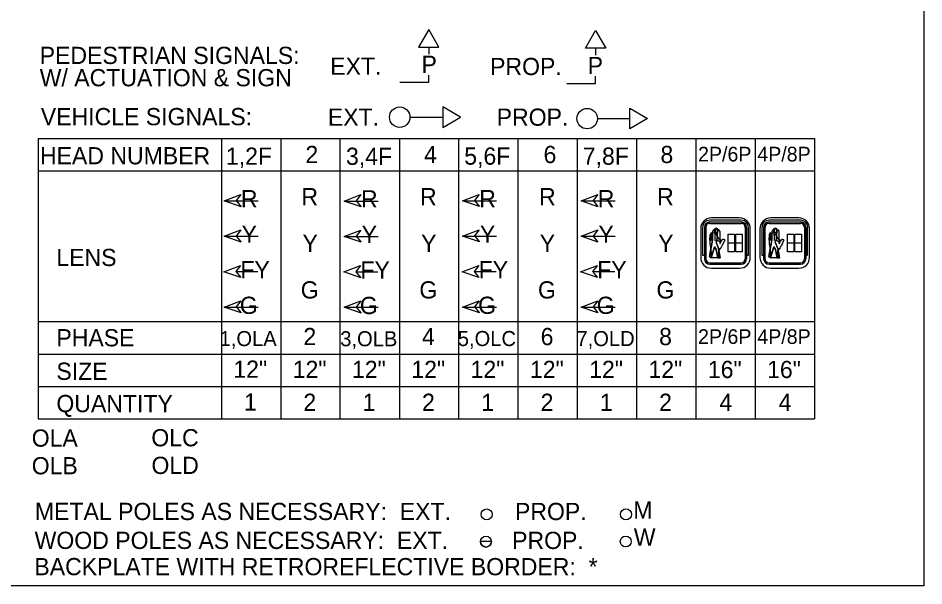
# Model space of a CAD drawing. Extents: x 0 to 3.01, y -0.05 to 1.83.
# Drawn here: x 0.2563 to 0.7077, y 1.2823 to 1.5653 of the extents above; entities that cross this region are included whole.
import ezdxf

# ---------------------------------------------------------------- set-up
doc = ezdxf.new("R2010")
doc.units = 0
for name, color, linetype in [('Default', 7, 'Continuous'), ('TR_TS_Border', 7, 'Continuous'), ('TR_TS_Phase1', 7, 'Continuous'), ('TR_TS_Phase2', 7, 'Continuous'), ('TR_TS_Phase3', 7, 'Continuous'), ('TR_TS_Phase4', 7, 'Continuous'), ('TR_TS_Phase5', 7, 'Continuous'), ('TR_TS_Phase6', 7, 'Continuous'), ('TR_TS_Phase7', 7, 'Continuous'), ('TR_TS_Phase8', 7, 'Continuous'), ('TR_TS_Text', 7, 'Continuous')]:
    doc.layers.add(name, color=color, linetype=linetype)

msp = doc.modelspace()

# ---------------------------------------------------------------- linework, layer by layer
at = {"layer": 'TR_TS_Border'}
for p, q in [((0.46095, 1.55972), (0.45582, 1.55087)), ((0.46607, 1.55087), (0.46095, 1.55972)), ((0.53902, 1.55029), (0.54415, 1.55914)), ((0.54415, 1.55914), (0.54927, 1.55029)), ((0.45582, 1.55087), (0.46607, 1.55087)), ((0.46094, 1.55087), (0.46094, 1.54739)), ((0.54927, 1.55029), (0.53902, 1.55029)), ((0.54414, 1.55029), (0.54414, 1.54681)), ((0.46094, 1.53335), (0.46094, 1.53689)), ((0.54414, 1.53278), (0.54414, 1.53632)), ((0.44653, 1.53335), (0.46094, 1.53335)), ((0.52973, 1.53278), (0.54414, 1.53278)), ((0.47683, 1.51599), (0.46798, 1.52105)), ((0.46798, 1.52105), (0.46798, 1.51087)), ((0.56115, 1.51017), (0.56116, 1.52035)), ((0.56116, 1.52035), (0.57001, 1.51529)), ((0.45159, 1.516), (0.46771, 1.516)), ((0.46798, 1.51087), (0.47683, 1.51599)), ((0.54503, 1.51529), (0.56116, 1.51529)), ((0.57001, 1.51529), (0.56115, 1.51017)), ((0.26627, 1.50537), (0.65319, 1.50537)), ((0.26627, 1.50537), (0.26627, 1.36564)), ((0.35762, 1.50537), (0.35762, 1.36564)), ((0.35762, 1.50537), (0.35762, 1.36564)), ((0.38721, 1.50537), (0.38721, 1.36564)), ((0.41674, 1.50537), (0.41674, 1.36564)), ((0.44632, 1.50537), (0.44632, 1.36564)), ((0.47585, 1.50537), (0.47585, 1.36564)), ((0.50544, 1.50537), (0.50544, 1.36564)), ((0.53496, 1.50537), (0.53496, 1.36564)), ((0.56455, 1.50537), (0.56455, 1.36564)), ((0.59407, 1.50537), (0.59407, 1.36564)), ((0.62366, 1.50537), (0.62366, 1.36564)), ((0.62366, 1.50537), (0.62366, 1.36564)), ((0.65319, 1.50537), (0.65319, 1.36564)), ((0.65319, 1.50537), (0.65319, 1.36564)), ((0.26627, 1.48924), (0.65319, 1.48924)), ((0.26627, 1.41401), (0.65319, 1.41401)), ((0.26627, 1.39789), (0.65319, 1.39789)), ((0.26627, 1.38177), (0.65319, 1.38177)), ((0.26627, 1.36564), (0.65319, 1.36564)), ((0.49219, 1.30439), (0.48676, 1.30439))]:
    msp.add_line(p, q, dxfattribs=at)
msp.add_lwpolyline([(0.20262, 1.70195), (0.70772, 1.70191), (0.70768, 1.2823), (0.20258, 1.28235)], close=True, dxfattribs=at)
for centre, radius in [((0.44651, 1.51592), 0.0051), ((0.53995, 1.51522), 0.0051), ((0.48986, 1.31794), 0.00273), ((0.55926, 1.31796), 0.00272), ((0.48947, 1.3044), 0.00273), ((0.55914, 1.30442), 0.00272)]:
    msp.add_circle(centre, radius, dxfattribs=at)
msp.add_arc((0.48947, 1.30439), 0.00272, 179.995, 359.995, dxfattribs=at)
at = {"layer": 'TR_TS_Phase1'}
for p, q in [((0.35905, 1.47423), (0.36738, 1.4774)), ((0.36738, 1.4774), (0.36499, 1.47433)), ((0.35905, 1.47423), (0.37596, 1.47423)), ((0.36746, 1.47133), (0.35905, 1.47423)), ((0.36499, 1.47433), (0.36746, 1.47133)), ((0.35905, 1.45659), (0.36738, 1.45976)), ((0.36738, 1.45976), (0.36499, 1.4567)), ((0.35905, 1.45659), (0.37596, 1.45659)), ((0.36746, 1.4537), (0.35905, 1.45659)), ((0.36499, 1.4567), (0.36746, 1.4537)), ((0.35883, 1.43887), (0.36717, 1.44204)), ((0.36717, 1.44204), (0.36478, 1.43898)), ((0.36725, 1.43598), (0.35883, 1.43887)), ((0.36478, 1.43898), (0.37582, 1.43898)), ((0.36478, 1.43898), (0.36725, 1.43598)), ((0.35905, 1.42124), (0.36738, 1.42441)), ((0.36738, 1.42441), (0.36499, 1.42134)), ((0.35905, 1.42124), (0.37596, 1.42124)), ((0.36746, 1.41835), (0.35905, 1.42124)), ((0.36499, 1.42134), (0.36746, 1.41835))]:
    msp.add_line(p, q, dxfattribs=at)
at = {"layer": 'TR_TS_Phase3'}
for p, q in [((0.41888, 1.47415), (0.42721, 1.47732)), ((0.42721, 1.47732), (0.42482, 1.47425)), ((0.41888, 1.47415), (0.43579, 1.47415)), ((0.42729, 1.47125), (0.41888, 1.47415)), ((0.42482, 1.47425), (0.42729, 1.47125)), ((0.41888, 1.45651), (0.42721, 1.45968)), ((0.42721, 1.45968), (0.42482, 1.45662)), ((0.41888, 1.45651), (0.43579, 1.45651)), ((0.42729, 1.45362), (0.41888, 1.45651)), ((0.42482, 1.45662), (0.42729, 1.45362)), ((0.41866, 1.43879), (0.427, 1.44196)), ((0.427, 1.44196), (0.42461, 1.4389)), ((0.42708, 1.4359), (0.41866, 1.43879)), ((0.42461, 1.4389), (0.43565, 1.4389)), ((0.42461, 1.4389), (0.42708, 1.4359)), ((0.41888, 1.42116), (0.42721, 1.42433)), ((0.42721, 1.42433), (0.42482, 1.42126)), ((0.41888, 1.42116), (0.43579, 1.42116)), ((0.42729, 1.41827), (0.41888, 1.42116)), ((0.42482, 1.42126), (0.42729, 1.41827))]:
    msp.add_line(p, q, dxfattribs=at)
at = {"layer": 'TR_TS_Phase5'}
for p, q in [((0.47781, 1.47425), (0.48615, 1.47742)), ((0.48615, 1.47742), (0.48376, 1.47435)), ((0.47781, 1.47425), (0.49472, 1.47425)), ((0.48623, 1.47135), (0.47781, 1.47425)), ((0.48376, 1.47435), (0.48623, 1.47135)), ((0.47781, 1.45661), (0.48615, 1.45978)), ((0.48615, 1.45978), (0.48376, 1.45672)), ((0.47781, 1.45661), (0.49472, 1.45661)), ((0.48623, 1.45372), (0.47781, 1.45661)), ((0.48376, 1.45672), (0.48623, 1.45372)), ((0.4776, 1.43889), (0.48593, 1.44206)), ((0.48593, 1.44206), (0.48354, 1.439)), ((0.48601, 1.436), (0.4776, 1.43889)), ((0.48354, 1.439), (0.49459, 1.439)), ((0.48354, 1.439), (0.48601, 1.436)), ((0.47781, 1.42126), (0.48615, 1.42443)), ((0.48615, 1.42443), (0.48376, 1.42136)), ((0.47781, 1.42126), (0.49472, 1.42126)), ((0.48623, 1.41837), (0.47781, 1.42126)), ((0.48376, 1.42136), (0.48623, 1.41837))]:
    msp.add_line(p, q, dxfattribs=at)
at = {"layer": 'TR_TS_Phase7'}
for p, q in [((0.53688, 1.47423), (0.54522, 1.4774)), ((0.54522, 1.4774), (0.54283, 1.47433)), ((0.53688, 1.47423), (0.55379, 1.47423)), ((0.5453, 1.47133), (0.53688, 1.47423)), ((0.54283, 1.47433), (0.5453, 1.47133)), ((0.53688, 1.45659), (0.54522, 1.45976)), ((0.54522, 1.45976), (0.54283, 1.4567)), ((0.53688, 1.45659), (0.55379, 1.45659)), ((0.5453, 1.4537), (0.53688, 1.45659)), ((0.54283, 1.4567), (0.5453, 1.4537)), ((0.53666, 1.43887), (0.545, 1.44204)), ((0.545, 1.44204), (0.54261, 1.43898)), ((0.54508, 1.43598), (0.53666, 1.43887)), ((0.54261, 1.43898), (0.55366, 1.43898)), ((0.54261, 1.43898), (0.54508, 1.43598)), ((0.53688, 1.42124), (0.54522, 1.42441)), ((0.54522, 1.42441), (0.54283, 1.42134)), ((0.53688, 1.42124), (0.55379, 1.42124)), ((0.5453, 1.41835), (0.53688, 1.42124)), ((0.54283, 1.42134), (0.5453, 1.41835))]:
    msp.add_line(p, q, dxfattribs=at)
at = {"layer": 'TR_TS_Text'}
for p, q in [((0.61669, 1.46461), (0.60101, 1.46461)), ((0.60101, 1.46369), (0.61669, 1.46369)), ((0.60101, 1.46302), (0.61669, 1.46302)), ((0.61586, 1.46569), (0.60184, 1.46569)), ((0.64622, 1.46461), (0.63054, 1.46461)), ((0.63054, 1.46369), (0.64622, 1.46369)), ((0.63054, 1.46302), (0.64622, 1.46302)), ((0.64538, 1.46569), (0.63137, 1.46569)), ((0.59651, 1.46035), (0.59651, 1.44601)), ((0.59742, 1.46102), (0.59742, 1.44717)), ((0.59834, 1.46102), (0.59834, 1.44534)), ((0.59901, 1.46102), (0.59901, 1.44534)), ((0.60123, 1.45729), (0.6027, 1.45819)), ((0.6026, 1.45448), (0.60256, 1.45913)), ((0.6027, 1.45819), (0.6027, 1.4582)), ((0.60349, 1.45913), (0.60352, 1.45449)), ((0.60369, 1.45449), (0.60382, 1.45986)), ((0.60475, 1.45986), (0.60461, 1.45445)), ((0.60478, 1.45445), (0.60505, 1.45922)), ((0.60596, 1.4591), (0.60596, 1.4531)), ((0.61869, 1.46102), (0.61869, 1.44534)), ((0.61936, 1.46102), (0.61936, 1.44534)), ((0.62028, 1.44717), (0.62028, 1.46102)), ((0.6212, 1.44601), (0.6212, 1.46035)), ((0.62603, 1.46035), (0.62603, 1.44601)), ((0.62695, 1.46102), (0.62695, 1.44717)), ((0.62787, 1.46102), (0.62787, 1.44534)), ((0.62853, 1.46102), (0.62853, 1.44534)), ((0.63075, 1.45729), (0.63222, 1.45819)), ((0.63212, 1.45448), (0.63209, 1.45913)), ((0.63222, 1.45819), (0.63222, 1.4582)), ((0.63301, 1.45913), (0.63305, 1.45449)), ((0.63322, 1.45449), (0.63335, 1.45986)), ((0.63427, 1.45986), (0.63414, 1.45445)), ((0.63431, 1.45445), (0.63458, 1.45922)), ((0.63548, 1.4591), (0.63548, 1.4531)), ((0.64822, 1.46102), (0.64822, 1.44534)), ((0.64889, 1.46102), (0.64889, 1.44534)), ((0.6498, 1.44717), (0.6498, 1.46102)), ((0.65072, 1.44601), (0.65072, 1.46035)), ((0.60093, 1.44657), (0.60227, 1.45378)), ((0.60101, 1.45458), (0.60123, 1.45729)), ((0.60164, 1.45461), (0.60101, 1.45458)), ((0.60128, 1.45245), (0.60133, 1.45762)), ((0.60194, 1.45704), (0.60164, 1.45461)), ((0.60233, 1.45704), (0.60194, 1.45704)), ((0.60208, 1.45568), (0.60233, 1.45704)), ((0.60229, 1.45762), (0.60243, 1.45448)), ((0.60243, 1.45448), (0.6026, 1.45448)), ((0.60352, 1.45449), (0.60369, 1.45449)), ((0.60415, 1.45359), (0.6054, 1.45044)), ((0.6051, 1.45433), (0.6044, 1.45502)), ((0.60445, 1.4574), (0.60535, 1.45525)), ((0.60461, 1.45445), (0.60478, 1.45445)), ((0.60631, 1.45384), (0.6051, 1.45433)), ((0.60535, 1.45525), (0.6066, 1.45455)), ((0.60627, 1.453), (0.60673, 1.45402)), ((0.6066, 1.45455), (0.60631, 1.45384)), ((0.60848, 1.45488), (0.607, 1.4516)), ((0.63045, 1.44657), (0.63179, 1.45378)), ((0.63054, 1.45458), (0.63075, 1.45729)), ((0.63116, 1.45461), (0.63054, 1.45458)), ((0.6308, 1.45245), (0.63085, 1.45762)), ((0.63147, 1.45704), (0.63116, 1.45461)), ((0.63185, 1.45704), (0.63147, 1.45704)), ((0.6316, 1.45568), (0.63185, 1.45704)), ((0.63182, 1.45762), (0.63196, 1.45448)), ((0.63196, 1.45448), (0.63212, 1.45448)), ((0.63305, 1.45449), (0.63322, 1.45449)), ((0.63368, 1.45359), (0.63492, 1.45044)), ((0.63463, 1.45433), (0.63392, 1.45502)), ((0.63398, 1.4574), (0.63487, 1.45525)), ((0.63414, 1.45445), (0.63431, 1.45445)), ((0.63584, 1.45384), (0.63463, 1.45433)), ((0.63487, 1.45525), (0.63612, 1.45455)), ((0.6358, 1.453), (0.63626, 1.45402)), ((0.63612, 1.45455), (0.63584, 1.45384)), ((0.638, 1.45488), (0.63652, 1.4516)), ((0.60179, 1.44921), (0.60162, 1.44964)), ((0.60333, 1.45137), (0.60172, 1.44584)), ((0.60424, 1.45001), (0.60333, 1.45137)), ((0.60504, 1.44584), (0.60424, 1.45001)), ((0.60529, 1.44897), (0.60529, 1.44647)), ((0.6054, 1.45044), (0.60628, 1.44584)), ((0.60657, 1.45088), (0.60543, 1.44943)), ((0.61015, 1.45323), (0.61339, 1.45323)), ((0.61395, 1.45323), (0.61719, 1.45323)), ((0.63131, 1.44921), (0.63114, 1.44964)), ((0.63286, 1.45137), (0.63125, 1.44584)), ((0.63377, 1.45001), (0.63286, 1.45137)), ((0.63457, 1.44584), (0.63377, 1.45001)), ((0.63481, 1.44897), (0.63481, 1.44647)), ((0.63492, 1.45044), (0.63581, 1.44584)), ((0.6361, 1.45088), (0.63496, 1.44943)), ((0.63967, 1.45323), (0.64292, 1.45323)), ((0.64347, 1.45323), (0.64672, 1.45323)), ((0.59742, 1.44717), (0.59834, 1.44717)), ((0.60172, 1.44584), (0.60093, 1.44657)), ((0.60568, 1.44584), (0.60153, 1.44584)), ((0.60193, 1.44647), (0.60193, 1.44843)), ((0.60628, 1.44584), (0.60504, 1.44584)), ((0.6194, 1.44717), (0.62028, 1.44717)), ((0.62695, 1.44717), (0.62786, 1.44717)), ((0.63125, 1.44584), (0.63045, 1.44657)), ((0.63521, 1.44584), (0.63106, 1.44584)), ((0.63145, 1.44647), (0.63145, 1.44843)), ((0.63581, 1.44584), (0.63457, 1.44584)), ((0.64893, 1.44717), (0.6498, 1.44717)), ((0.60101, 1.44334), (0.61669, 1.44334)), ((0.60101, 1.44267), (0.61669, 1.44267)), ((0.60184, 1.44067), (0.61586, 1.44067)), ((0.63054, 1.44334), (0.64622, 1.44334)), ((0.63054, 1.44267), (0.64622, 1.44267)), ((0.63137, 1.44067), (0.64538, 1.44067))]:
    msp.add_line(p, q, dxfattribs=at)
for points in [[(0.6027, 1.4582), (0.60123, 1.45729), (0.60101, 1.45458), (0.60164, 1.45461), (0.60194, 1.45704), (0.60233, 1.45704), (0.60208, 1.45568)], [(0.63222, 1.4582), (0.63075, 1.45729), (0.63054, 1.45458), (0.63116, 1.45461), (0.63147, 1.45704), (0.63185, 1.45704), (0.6316, 1.45568)], [(0.60227, 1.45378), (0.60093, 1.44657), (0.60172, 1.44584), (0.60333, 1.45137), (0.60424, 1.45001), (0.60504, 1.44584), (0.60628, 1.44584), (0.6054, 1.45044), (0.60415, 1.45359)], [(0.6044, 1.45502), (0.6051, 1.45433), (0.60631, 1.45384), (0.6066, 1.45455), (0.60535, 1.45525), (0.60445, 1.4574)], [(0.63179, 1.45378), (0.63045, 1.44657), (0.63125, 1.44584), (0.63286, 1.45137), (0.63377, 1.45001), (0.63457, 1.44584), (0.63581, 1.44584), (0.63492, 1.45044), (0.63368, 1.45359)], [(0.63392, 1.45502), (0.63463, 1.45433), (0.63584, 1.45384), (0.63612, 1.45455), (0.63487, 1.45525), (0.63398, 1.4574)]]:
    msp.add_lwpolyline(points, dxfattribs=at)
for points in [[(0.61015, 1.45757), (0.61339, 1.45757), (0.61339, 1.4489), (0.61015, 1.4489)], [(0.61395, 1.45757), (0.61719, 1.45757), (0.61719, 1.4489), (0.61395, 1.4489)], [(0.63967, 1.45757), (0.64292, 1.45757), (0.64292, 1.4489), (0.63967, 1.4489)], [(0.64347, 1.45757), (0.64672, 1.45757), (0.64672, 1.4489), (0.64347, 1.4489)]]:
    msp.add_lwpolyline(points, close=True, dxfattribs=at)
for centre in [(0.6042, 1.4595), (0.63372, 1.4595)]:
    msp.add_circle(centre, 0.00104, dxfattribs=at)
for centre, radius, start, end in [((0.60184, 1.46035), 0.00534, 90, 180), ((0.60101, 1.46102), 0.00359, 90, 180), ((0.60101, 1.46102), 0.00267, 90, 180), ((0.60101, 1.46102), 0.002, 90, 180), ((0.61586, 1.46035), 0.00534, 360, 90), ((0.61669, 1.46102), 0.00359, 360, 90), ((0.61669, 1.46102), 0.00267, 360, 90), ((0.61669, 1.46102), 0.002, 360, 90), ((0.63137, 1.46035), 0.00534, 90, 180), ((0.63054, 1.46102), 0.00359, 90, 180), ((0.63054, 1.46102), 0.00267, 90, 180), ((0.63054, 1.46102), 0.002, 90, 180), ((0.64538, 1.46035), 0.00534, 360, 90), ((0.64622, 1.46102), 0.00359, 360, 90), ((0.64622, 1.46102), 0.00267, 360, 90), ((0.64622, 1.46102), 0.002, 360, 90), ((0.60315, 1.45686), 0.00141, 22.5543, 108.8346), ((0.60315, 1.45686), 0.00141, 22.5543, 108.8346), ((0.6042, 1.4595), 0.00104, 360, 180), ((0.6042, 1.4595), 0.00104, 180, 360), ((0.63268, 1.45686), 0.00141, 22.5543, 108.8346), ((0.63268, 1.45686), 0.00141, 22.5543, 108.8346), ((0.63372, 1.4595), 0.00104, 360, 180), ((0.63372, 1.4595), 0.00104, 180, 360), ((0.60937, 1.45546), 0.00729, 178.2568, 193.3072), ((0.60937, 1.45546), 0.00729, 178.2568, 193.3072), ((0.62269, 1.45117), 0.0187, 168.1276, 172.5821), ((0.62269, 1.45117), 0.0187, 168.1276, 172.5821), ((0.63889, 1.45546), 0.00729, 178.2568, 193.3072), ((0.63889, 1.45546), 0.00729, 178.2568, 193.3072), ((0.65222, 1.45117), 0.0187, 168.1276, 172.5821), ((0.65222, 1.45117), 0.0187, 168.1276, 172.5821), ((0.60184, 1.44601), 0.00534, 180, 270), ((0.60101, 1.44534), 0.00267, 180, 270), ((0.60101, 1.44534), 0.002, 180, 270), ((0.61586, 1.44601), 0.00534, 270, 360), ((0.61669, 1.44534), 0.00267, 270, 360), ((0.61669, 1.44534), 0.002, 270, 360), ((0.63137, 1.44601), 0.00534, 180, 270), ((0.63054, 1.44534), 0.00267, 180, 270), ((0.63054, 1.44534), 0.002, 180, 270), ((0.64538, 1.44601), 0.00534, 270, 360), ((0.64622, 1.44534), 0.00267, 270, 360), ((0.64622, 1.44534), 0.002, 270, 360)]:
    msp.add_arc(centre, radius, start, end, dxfattribs=at)
for centre, major_axis, start_param, end_param in [((0.60181, 1.45762), (0, 0.000619), 4.712477, 7.854069), ((0.60303, 1.45913), (0, 0.000592), 4.712394, 7.853977), ((0.60428, 1.45986), (0, 0.000592), 4.71238, 7.853968), ((0.6055, 1.45914), (0, 0.000581), 4.648575, 7.711685), ((0.63134, 1.45762), (0, 0.000619), 4.712477, 7.854069), ((0.63255, 1.45913), (0, 0.000592), 4.712394, 7.853977), ((0.63381, 1.45986), (0, 0.000592), 4.71238, 7.853968), ((0.63503, 1.45914), (0, 0.000581), 4.648575, 7.711685), ((0.60792, 1.45338), (0, 0.00165), 5.840541, 7.460675), ((0.63745, 1.45338), (0, 0.00165), 5.840541, 7.460675), ((0.60799, 1.45234), (0, 0.00861), 1.557894, 1.890309), ((0.60059, 1.44843), (0, 0.00172), 4.712389, 5.179357), ((0.60579, 1.44897), (0, -0.000646), 3.926991, 4.712389), ((0.60613, 1.4531), (0, -0.000215), 4.712389, 7.330375), ((0.60467, 1.45332), (0, -0.00344), 0.785398, 1.047195), ((0.63752, 1.45234), (0, 0.00861), 1.557894, 1.890309), ((0.63011, 1.44843), (0, 0.00172), 4.712389, 5.179357), ((0.63531, 1.44897), (0, -0.000646), 3.926991, 4.712389), ((0.63565, 1.4531), (0, -0.000215), 4.712389, 7.330375), ((0.6342, 1.45332), (0, -0.00344), 0.785398, 1.047195), ((0.60143, 1.44647), (0, 0.000646), 3.359088, 4.712389), ((0.60579, 1.44647), (0, -0.000646), 4.712389, 6.06569), ((0.63095, 1.44647), (0, 0.000646), 3.359088, 4.712389), ((0.63531, 1.44647), (0, -0.000646), 4.712389, 6.06569)]:
    msp.add_ellipse(centre, major_axis=major_axis, ratio=0.780287, start_param=start_param, end_param=end_param, dxfattribs=at)

# ---------------------------------------------------------------- texts
at = {"layer": 'Default'}
for s, p in [('PEDESTRIAN SIGNALS:', (0.2671, 1.54245)), ('W/ ACTUATION & SIGN', (0.2671, 1.53134))]:
    msp.add_text(s, height=0.0085848, dxfattribs=at).set_placement(p)
at = {"layer": 'TR_TS_Border'}
for s, height, p in [('EXT.', 0.008585, (0.41188, 1.53706)), ('P', 0.00858, (0.45737, 1.538)), ('PROP.', 0.008585, (0.49154, 1.53692)), ('P', 0.00858, (0.54017, 1.53742)), ('VEHICLE SIGNALS:', 0.0085848, (0.26766, 1.51193)), ('EXT.', 0.008585, (0.41069, 1.51167)), ('PROP.', 0.008585, (0.49483, 1.51166)), ('METAL POLES AS NECESSARY:  EXT.          PROP.', 0.0085848, (0.26471, 1.31513)), ('M', 0.00858, (0.5629, 1.31581)), ('WOOD POLES AS NECESSARY:  EXT.          PROP.', 0.0085848, (0.26457, 1.30072)), ('W', 0.00858, (0.56316, 1.30235)), ('BACKPLATE WITH RETROREFLECTIVE BORDER:  *', 0.0085848, (0.26445, 1.28762))]:
    msp.add_text(s, height=height, rotation=359.995, dxfattribs=at).set_placement(p)
for s, height, p in [('HEAD NUMBER', 0.0085848, (0.26723, 1.49243)), ('LENS', 0.008585, (0.27541, 1.44172)), ('PHASE', 0.008585, (0.27541, 1.4017)), ('SIZE', 0.008585, (0.27541, 1.38501)), ('QUANTITY', 0.008585, (0.27541, 1.36889)), ('OLA', 0.008578, (0.26313, 1.35171)), ('OLC', 0.008578, (0.32273, 1.35188)), ('OLB', 0.008578, (0.26313, 1.33792)), ('OLD', 0.008578, (0.32281, 1.33809))]:
    msp.add_text(s, height=height, dxfattribs=at).set_placement(p)
at = {"layer": 'TR_TS_Phase1'}
for s, height, p in [('1,2F', 0.008585, (0.3599, 1.49223)), ('R', 0.00858, (0.36737, 1.47104)), (' Y ', 0.008585, (0.36451, 1.45331)), ('FY', 0.008585, (0.36709, 1.43559)), (' G ', 0.008585, (0.36363, 1.41787)), ('1,OLA', 0.007506, (0.35675, 1.40183))]:
    msp.add_text(s, height=height, rotation=360, dxfattribs=at).set_placement(p)
for s, p in [('12"', (0.3636, 1.38603)), (' 1 ', (0.36573, 1.36965))]:
    msp.add_text(s, height=0.008585, dxfattribs=at).set_placement(p)
at = {"layer": 'TR_TS_Phase2'}
for s, height, p in [('2', 0.00858, (0.39951, 1.49306)), (' R ', 0.008585, (0.39432, 1.47205)), (' Y ', 0.008585, (0.39487, 1.4488)), (' G ', 0.008585, (0.39399, 1.42555)), (' 2 ', 0.008585, (0.39532, 1.4023)), ('12"', 0.008585, (0.39318, 1.38592)), (' 2 ', 0.008585, (0.39532, 1.36954))]:
    msp.add_text(s, height=height, dxfattribs=at).set_placement(p)
at = {"layer": 'TR_TS_Phase3'}
for s, height, p in [('3,4F', 0.008585, (0.41973, 1.49215)), ('R', 0.00858, (0.4272, 1.47096)), (' Y ', 0.008585, (0.42434, 1.45323)), ('FY', 0.008585, (0.42692, 1.43551)), (' G ', 0.008585, (0.42346, 1.41779)), ('3,OLB', 0.007506, (0.41687, 1.40175))]:
    msp.add_text(s, height=height, rotation=360, dxfattribs=at).set_placement(p)
for s, p in [('12"', (0.42271, 1.38592)), (' 1 ', (0.42484, 1.36954))]:
    msp.add_text(s, height=0.008585, dxfattribs=at).set_placement(p)
at = {"layer": 'TR_TS_Phase4'}
for s, height, p in [('4', 0.00858, (0.45864, 1.49306)), (' R ', 0.008585, (0.45343, 1.47205)), (' Y ', 0.008585, (0.45398, 1.4488)), (' G ', 0.008585, (0.4531, 1.42555)), (' 4 ', 0.008585, (0.45443, 1.4023)), ('12"', 0.008585, (0.4523, 1.38592)), (' 2 ', 0.008585, (0.45443, 1.36954))]:
    msp.add_text(s, height=height, dxfattribs=at).set_placement(p)
at = {"layer": 'TR_TS_Phase5'}
for s, height, p in [('5,6F', 0.008585, (0.47866, 1.49225)), ('R', 0.00858, (0.48614, 1.47106)), (' Y ', 0.008585, (0.48327, 1.45333)), ('FY', 0.008585, (0.48585, 1.43561)), (' G ', 0.008585, (0.48239, 1.41789)), ('5,OLC', 0.007506, (0.47544, 1.40185))]:
    msp.add_text(s, height=height, rotation=360, dxfattribs=at).set_placement(p)
for s, p in [('12"', (0.48182, 1.38592)), (' 1 ', (0.48395, 1.36954))]:
    msp.add_text(s, height=0.008585, dxfattribs=at).set_placement(p)
at = {"layer": 'TR_TS_Phase6'}
for s, height, p in [('6', 0.00858, (0.51818, 1.49306)), ('R', 0.00858, (0.51596, 1.47205)), (' Y ', 0.008585, (0.51309, 1.4488)), (' G ', 0.008585, (0.51221, 1.42555)), (' 6 ', 0.008585, (0.51354, 1.4023)), ('12"', 0.008585, (0.51141, 1.38592)), (' 2 ', 0.008585, (0.51354, 1.36954))]:
    msp.add_text(s, height=height, dxfattribs=at).set_placement(p)
at = {"layer": 'TR_TS_Phase7'}
for s, height, p in [('7,8F', 0.008585, (0.53773, 1.49223)), ('R', 0.00858, (0.5452, 1.47104)), (' Y ', 0.008585, (0.54234, 1.45331)), ('FY', 0.008585, (0.54492, 1.43559)), (' G ', 0.008585, (0.54146, 1.41787)), ('7,OLD', 0.007506, (0.53458, 1.40183))]:
    msp.add_text(s, height=height, rotation=360, dxfattribs=at).set_placement(p)
for s, p in [('12"', (0.54093, 1.38592)), (' 1 ', (0.54307, 1.36954))]:
    msp.add_text(s, height=0.008585, dxfattribs=at).set_placement(p)
at = {"layer": 'TR_TS_Phase8'}
for s, height, p in [('8', 0.00858, (0.57644, 1.49306)), (' R ', 0.008585, (0.57159, 1.47205)), (' Y ', 0.008585, (0.57214, 1.4488)), (' G ', 0.008585, (0.57126, 1.42555)), (' 8 ', 0.008585, (0.57259, 1.4023)), ('12"', 0.008585, (0.57046, 1.38592)), (' 2 ', 0.008585, (0.57259, 1.36954))]:
    msp.add_text(s, height=height, dxfattribs=at).set_placement(p)
at = {"layer": 'TR_TS_Text'}
for s, height, p in [('2P/6P', 0.007298, (0.59519, 1.49387)), ('4P/8P', 0.007298, (0.62472, 1.49387)), ('2P/6P', 0.007298, (0.59519, 1.40293)), ('4P/8P', 0.007298, (0.62472, 1.40293)), ('16"', 0.008585, (0.60006, 1.3859)), ('16"', 0.008585, (0.62958, 1.3859)), ('4', 0.00858, (0.60581, 1.36952)), ('4', 0.00858, (0.63534, 1.36952))]:
    msp.add_text(s, height=height, rotation=360, dxfattribs=at).set_placement(p)

doc.saveas('drawing.dxf')
